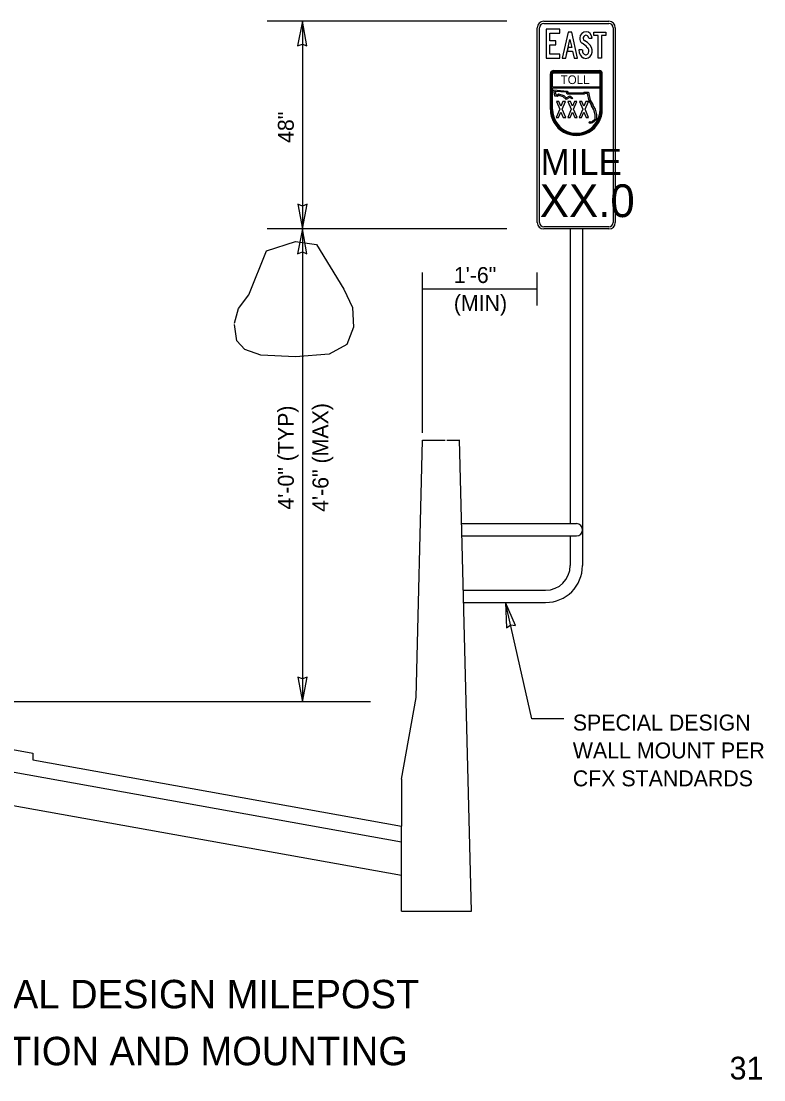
# Model space of a CAD drawing. Extents: x 57428 to 58066, y 11696 to 12105.
# Drawn here: x 57924.4 to 58054.8, y 11706.5 to 11892.4 of the extents above; entities that cross this region are included whole.
import ezdxf

# ---------------------------------------------------------------- set-up
doc = ezdxf.new("R2010")
doc.units = 0
for name, color, linetype in [('52', 7, 'Continuous'), ('62', 7, 'Continuous'), ('DimLines_dp', 7, 'Continuous'), ('NonPlottingEle_dp', 7, 'Continuous'), ('SheetLines_dp', 7, 'Continuous'), ('SignPanel', 7, 'Continuous'), ('TextMinor', 7, 'Continuous'), ('XSGrdLine_ex', 7, 'Continuous')]:
    doc.layers.add(name, color=color, linetype=linetype)

msp = doc.modelspace()

# ---------------------------------------------------------------- linework, layer by layer
at = {"layer": '52'}
msp.add_line((57985.74, 11772.84), (57842.57, 11772.84), dxfattribs=at)
at = {"layer": '62'}
msp.add_lwpolyline([(57961.87, 11839.32), (57962.57, 11841.92), (57964.37, 11844.33), (57967.47, 11852.08), (57972.57, 11853.68), (57976.27, 11853.18), (57981.07, 11845.33), (57982.58, 11842.12), (57982.78, 11838.62), (57981.57, 11835.62), (57978.47, 11833.91), (57972.57, 11833.41), (57966.47, 11833.71), (57963.67, 11834.71), (57962.27, 11836.22), (57961.87, 11839.12)], dxfattribs=at)
at = {"layer": 'DimLines_dp'}
for p, q in [((58009.68, 11892.38), (57967.6, 11892.38)), ((57973.78, 11892.38), (57972.94, 11888.03)), ((57973.78, 11892.38), (57973.78, 11855.89)), ((57974.59, 11888.03), (57973.78, 11892.38)), ((57972.94, 11888.03), (57973.78, 11888.36)), ((57973.78, 11888.36), (57974.59, 11888.03)), ((57973.78, 11861.88), (57973.78, 11772.84)), ((57973.78, 11859.91), (57972.97, 11860.24)), ((57972.97, 11860.24), (57973.78, 11855.89)), ((57973.78, 11859.91), (57972.97, 11860.24)), ((57972.97, 11860.24), (57973.78, 11855.89)), ((57973.78, 11855.89), (57974.62, 11860.24)), ((57974.62, 11860.24), (57973.78, 11859.91)), ((57973.78, 11855.89), (57974.62, 11860.24)), ((57974.62, 11860.24), (57973.78, 11859.91)), ((58009.68, 11855.89), (57967.6, 11855.89)), ((57973.78, 11855.89), (57972.94, 11851.54)), ((57974.59, 11851.54), (57973.78, 11855.89)), ((57972.94, 11851.54), (57973.78, 11851.87)), ((57973.78, 11851.87), (57974.59, 11851.54)), ((57994.89, 11820.11), (57994.89, 11848.22)), ((58015.03, 11842.47), (58015.03, 11848.22)), ((57994.89, 11845.38), (58015.03, 11845.38)), ((58009.47, 11790.29), (58009.6, 11785.87)), ((58011.21, 11786.23), (58009.47, 11790.29)), ((58014.05, 11769.85), (58009.47, 11790.29)), ((58009.6, 11785.87), (58010.35, 11786.37)), ((58010.35, 11786.37), (58011.21, 11786.23)), ((57973.78, 11776.86), (57972.97, 11777.19)), ((57972.97, 11777.19), (57973.78, 11772.84)), ((57973.78, 11772.84), (57974.62, 11777.19)), ((57974.62, 11777.19), (57973.78, 11776.86)), ((58019.7, 11769.85), (58014.05, 11769.85))]:
    msp.add_line(p, q, dxfattribs=at)
at = {"layer": 'NonPlottingEle_dp'}
for p, q in [((58020.8, 11855.89), (58020.8, 11804.14)), ((58022.96, 11855.89), (58022.96, 11796.77)), ((58001.72, 11804.14), (58021.88, 11804.14)), ((58001.78, 11801.98), (58021.88, 11801.98)), ((58020.8, 11801.98), (58020.8, 11796.77)), ((58002.02, 11792.45), (58016.48, 11792.45)), ((58002.08, 11790.29), (58016.48, 11790.29))]:
    msp.add_line(p, q, dxfattribs=at)
for centre, radius, end in [((58021.88, 11803.06), 1.08, 90), ((58016.48, 11796.77), 4.32, 0), ((58016.48, 11796.77), 6.48, 0)]:
    msp.add_arc(centre, radius, 270, end, dxfattribs=at)
at = {"layer": 'SignPanel'}
for p, q in [((58024.07, 11889.38), (58024.65, 11889.38)), ((58024.07, 11889.38), (58024.65, 11889.38)), ((58024.07, 11889.38), (58024.65, 11889.38)), ((58022.93, 11887.34), (58022.34, 11887.34)), ((58022.93, 11887.34), (58022.34, 11887.34)), ((58022.93, 11887.34), (58022.34, 11887.34)), ((58017.32, 11876.87), (58017.32, 11883.15)), ((58017.51, 11876.87), (58017.51, 11883.15)), ((58017.69, 11880.87), (58017.69, 11883.15)), ((58017.89, 11883.72), (58025.87, 11883.72)), ((58017.89, 11883.53), (58025.87, 11883.53)), ((58017.89, 11883.33), (58025.87, 11883.33)), ((58026.06, 11880.87), (58026.06, 11883.15)), ((58026.25, 11876.87), (58026.25, 11883.15)), ((58026.44, 11876.87), (58026.44, 11883.15)), ((58017.69, 11880.87), (58026.06, 11880.87)), ((58017.69, 11876.87), (58017.69, 11880.67)), ((58017.69, 11880.67), (58026.06, 11880.67)), ((58026.06, 11876.87), (58026.06, 11880.67)), ((58018.08, 11879.22), (58017.91, 11880.31)), ((58017.91, 11880.31), (58020.29, 11880.12)), ((58018.53, 11879.16), (58018.08, 11879.22)), ((58020.13, 11879.91), (58018.18, 11880.06)), ((58018.18, 11880.06), (58018.28, 11879.43)), ((58018.28, 11879.43), (58018.47, 11879.4)), ((58018.47, 11879.4), (58018.74, 11879.61)), ((58018.78, 11879.36), (58018.53, 11879.16)), ((58018.74, 11879.61), (58019.66, 11879.32)), ((58019.54, 11879.11), (58018.78, 11879.36)), ((58019.17, 11879.97), (58019.17, 11879.97)), ((58020.08, 11878.61), (58019.54, 11879.11)), ((58019.66, 11879.32), (58020.11, 11878.9)), ((58020.71, 11878.99), (58020.08, 11878.61)), ((58020.11, 11878.9), (58020.72, 11879.26)), ((58020.27, 11879.55), (58020.13, 11879.91)), ((58023.27, 11879.55), (58020.27, 11879.55)), ((58020.29, 11880.12), (58020.42, 11879.78)), ((58020.42, 11879.78), (58023.15, 11879.78)), ((58021.09, 11878.73), (58020.71, 11878.99)), ((58020.72, 11879.26), (58021.22, 11878.92)), ((58021.22, 11878.92), (58021.09, 11878.73)), ((58023.15, 11879.78), (58023.26, 11879.93)), ((58023.26, 11879.93), (58023.99, 11879.93)), ((58023.38, 11879.7), (58023.27, 11879.55)), ((58023.81, 11879.7), (58023.38, 11879.7)), ((58024.11, 11878.41), (58023.81, 11879.7)), ((58023.99, 11879.93), (58024.32, 11878.5)), ((58024.32, 11878.5), (58024.78, 11877.78)), ((58024.55, 11877.71), (58024.11, 11878.41)), ((58024.55, 11877.53), (58024.55, 11877.71)), ((58024.97, 11876.83), (58024.55, 11877.53)), ((58024.78, 11877.78), (58024.78, 11877.59)), ((58024.78, 11877.59), (58025.19, 11876.92)), ((58025.21, 11875.96), (58024.97, 11876.83)), ((58025.19, 11876.92), (58025.44, 11875.99)), ((58024.1, 11874.59), (58024.23, 11874.78)), ((58024.23, 11874.78), (58024.37, 11874.68)), ((58024.58, 11874.73), (58025.21, 11875.24)), ((58025.44, 11875.13), (58024.69, 11874.52)), ((58025.21, 11875.24), (58025.21, 11875.96)), ((58025.44, 11875.99), (58025.44, 11875.13)), ((58024.33, 11874.43), (58024.1, 11874.59)), ((58024.69, 11874.52), (58024.33, 11874.43)), ((58024.37, 11874.68), (58024.58, 11874.73))]:
    msp.add_line(p, q, dxfattribs=at)
for points in [[(58016.17, 11892.38), (58027.58, 11892.38)], [(58016.17, 11892), (58027.58, 11892)], [(58015.03, 11857.03), (58015.03, 11891.24)], [(58015.41, 11857.03), (58015.41, 11891.24)], [(58028.34, 11891.24), (58028.34, 11857.03)], [(58028.72, 11891.24), (58028.72, 11857.03)], [(58027.58, 11856.27), (58016.17, 11856.27)], [(58027.58, 11855.89), (58016.17, 11855.89)]]:
    msp.add_lwpolyline(points, dxfattribs=at)
for points in [[(58017.24, 11886.61), (58017.24, 11888.23), (58018.26, 11888.23), (58018.26, 11888.94), (58017.24, 11888.94), (58017.24, 11890.26), (58018.96, 11890.26), (58018.96, 11890.97), (58016.58, 11890.97), (58016.58, 11885.9), (58018.96, 11885.9), (58018.96, 11886.61)], [(58017.24, 11886.61), (58017.24, 11888.23), (58018.26, 11888.23), (58018.26, 11888.94), (58017.24, 11888.94), (58017.24, 11890.26), (58018.96, 11890.26), (58018.96, 11890.97), (58016.58, 11890.97), (58016.58, 11885.9), (58018.96, 11885.9), (58018.96, 11886.61)], [(58017.24, 11886.61), (58017.24, 11888.23), (58018.26, 11888.23), (58018.26, 11888.94), (58017.24, 11888.94), (58017.24, 11890.26), (58018.96, 11890.26), (58018.96, 11890.97), (58016.58, 11890.97), (58016.58, 11885.9), (58018.96, 11885.9), (58018.96, 11886.61)], [(58021.21, 11887.13), (58021.48, 11885.9), (58022.08, 11885.9), (58021.06, 11890.48), (58020.43, 11890.48), (58019.41, 11885.9), (58020.02, 11885.9), (58020.29, 11887.13)], [(58020.44, 11887.77), (58020.29, 11887.13), (58021.21, 11887.13), (58021.48, 11885.9), (58022.08, 11885.9), (58021.06, 11890.48), (58020.43, 11890.48), (58019.41, 11885.9), (58020.02, 11885.9), (58020.75, 11889.17), (58021.06, 11887.77)], [(58020.44, 11887.77), (58020.29, 11887.13), (58021.21, 11887.13), (58021.48, 11885.9), (58022.08, 11885.9), (58021.06, 11890.48), (58020.43, 11890.48), (58019.41, 11885.9), (58020.02, 11885.9), (58020.75, 11889.17), (58021.06, 11887.77)], [(58025.72, 11889.84), (58024.94, 11889.84), (58024.94, 11890.48), (58027.08, 11890.48), (58027.08, 11889.84), (58026.3, 11889.84), (58026.3, 11885.9), (58025.72, 11885.9)], [(58025.72, 11889.84), (58024.94, 11889.84), (58024.94, 11890.48), (58027.08, 11890.48), (58027.08, 11889.84), (58026.3, 11889.84), (58026.3, 11885.9), (58025.72, 11885.9)], [(58025.72, 11889.84), (58024.94, 11889.84), (58024.94, 11890.48), (58027.08, 11890.48), (58027.08, 11889.84), (58026.3, 11889.84), (58026.3, 11885.9), (58025.72, 11885.9)], [(58020.75, 11889.17), (58021.06, 11887.77), (58020.44, 11887.77)], [(58018.77, 11875.45), (58019.17, 11876.43), (58019.58, 11875.45), (58020.01, 11875.45), (58019.39, 11876.94), (58019.96, 11878.3), (58019.53, 11878.3), (58019.17, 11877.45), (58018.82, 11878.3), (58018.39, 11878.3), (58018.96, 11876.94), (58018.34, 11875.45)], [(58020.78, 11875.45), (58021.19, 11876.43), (58021.6, 11875.45), (58022.03, 11875.45), (58021.4, 11876.94), (58021.98, 11878.3), (58021.55, 11878.3), (58021.19, 11877.45), (58020.83, 11878.3), (58020.41, 11878.3), (58020.98, 11876.94), (58020.36, 11875.45)], [(58022.8, 11875.45), (58023.21, 11876.43), (58023.61, 11875.45), (58024.04, 11875.45), (58023.42, 11876.94), (58023.99, 11878.3), (58023.56, 11878.3), (58023.21, 11877.45), (58022.85, 11878.3), (58022.42, 11878.3), (58022.99, 11876.94), (58022.37, 11875.45)]]:
    msp.add_lwpolyline(points, close=True, dxfattribs=at)
for centre, radius, start, end in [((58016.17, 11891.24), 1.14, 90, 180), ((58016.17, 11891.24), 0.76, 90, 180), ((58027.58, 11891.24), 1.14, 0, 90), ((58027.58, 11891.24), 0.76, 0, 90), ((58016.17, 11857.03), 1.14, 180, 270), ((58016.17, 11857.03), 0.76, 180, 270), ((58027.58, 11857.03), 1.14, 270, 360), ((58027.58, 11857.03), 0.76, 270, 360)]:
    msp.add_arc(centre, radius, start, end, dxfattribs=at)
for centre, major_axis, ratio, start_param, end_param in [((58023.56, 11889.35), (0, 1.19), 0.91923, 4.736267, 7.790596), ((58023.56, 11889.35), (0, 1.19), 0.91923, 4.736267, 7.790596), ((58023.56, 11889.35), (0, 1.19), 0.91923, 4.736267, 7.790596), ((58023.49, 11889.41), (0, 0.46), 0.91923, 0.87378, 2.656959), ((58023.49, 11889.41), (0, 0.46), 0.91923, 0.87378, 2.656959), ((58023.49, 11889.41), (0, 0.46), 0.91923, 0.87378, 2.656959), ((58023.56, 11889.34), (0, 0.558), 0.91923, 4.786904, 7.140738), ((58023.56, 11889.34), (0, 0.558), 0.91923, 4.786904, 7.140738), ((58023.56, 11889.34), (0, 0.558), 0.91923, 4.786904, 7.140738), ((58023.45, 11889.39), (0, 1.07), 0.91923, 1.534831, 2.511766), ((58023.45, 11889.39), (0, 1.07), 0.91923, 1.534831, 2.511766), ((58023.45, 11889.39), (0, 1.07), 0.91923, 1.534831, 2.511766), ((58020.85, 11884.45), (0, 4.63), 0.91923, 5.515137, 5.786988), ((58020.85, 11884.45), (0, 4.63), 0.91923, 5.515137, 5.786988), ((58020.85, 11884.45), (0, 4.63), 0.91923, 5.515137, 5.786988), ((58021.36, 11885.15), (0, 4.39), 0.91923, 5.462886, 5.782242), ((58021.36, 11885.15), (0, 4.39), 0.91923, 5.462886, 5.782242), ((58021.36, 11885.15), (0, 4.39), 0.91923, 5.462886, 5.782242), ((58023.37, 11887.15), (0, 0.792), 0.91923, 4.254409, 5.632398), ((58023.37, 11887.15), (0, 0.792), 0.91923, 4.254409, 5.632398), ((58023.37, 11887.15), (0, 0.792), 0.91923, 4.254409, 5.632398), ((58023.38, 11887.15), (0, 1.42), 0.91923, 4.260987, 5.485755), ((58023.38, 11887.15), (0, 1.42), 0.91923, 4.260987, 5.485755), ((58023.38, 11887.15), (0, 1.42), 0.91923, 4.260987, 5.485755), ((58023.71, 11887.27), (0, 1.5), 0.91923, 1.526364, 2.701682), ((58023.71, 11887.27), (0, 1.5), 0.91923, 1.526364, 2.701682), ((58023.71, 11887.27), (0, 1.5), 0.91923, 1.526364, 2.701682), ((58023.77, 11887.3), (0, 0.911), 0.91923, 1.524757, 2.28214), ((58023.77, 11887.3), (0, 0.911), 0.91923, 1.524757, 2.28214), ((58023.77, 11887.3), (0, 0.911), 0.91923, 1.524757, 2.28214), ((58023.53, 11887.08), (0, 1.24), 0.91923, 2.786047, 4.251692), ((58023.53, 11887.08), (0, 1.24), 0.91923, 2.786047, 4.251692), ((58023.53, 11887.08), (0, 1.24), 0.91923, 2.786047, 4.251692), ((58023.55, 11887.07), (0, 0.581), 0.91923, 2.261787, 4.23006), ((58023.55, 11887.07), (0, 0.581), 0.91923, 2.261787, 4.23006), ((58023.55, 11887.07), (0, 0.581), 0.91923, 2.261787, 4.23006), ((58017.89, 11883.14), (0, 0.57), 0.9997, 0, 1.570796), ((58017.89, 11883.14), (0, 0.38), 0.9997, 0, 1.570796), ((58017.89, 11883.14), (0, 0.19), 0.9997, 0, 1.570796), ((58025.87, 11883.14), (0, 0.57), 0.9997, 4.712389, 6.283185), ((58025.87, 11883.14), (0, 0.38), 0.9997, 4.712389, 6.283185), ((58025.87, 11883.14), (0, 0.19), 0.9997, 4.712389, 6.283185), ((58021.88, 11876.87), (0, -4.56), 0.9997, 4.712389, 7.853982), ((58021.88, 11876.87), (0, -4.37), 0.9997, 4.712389, 7.853982), ((58021.88, 11876.87), (0, -4.18), 0.9997, 4.712389, 7.853982)]:
    msp.add_ellipse(centre, major_axis=major_axis, ratio=ratio, start_param=start_param, end_param=end_param, dxfattribs=at)
at = {"layer": 'XSGrdLine_ex'}
for p, q in [((57993.74, 11773.63), (57994.89, 11818.81)), ((57994.89, 11818.81), (57998.87, 11818.81)), ((57999.15, 11818.81), (58001.35, 11818.81)), ((58003.46, 11736.1), (58001.35, 11818.87)), ((57991.17, 11759.25), (57993.74, 11773.63)), ((57920.31, 11764.96), (57926.48, 11763.85)), ((57926.48, 11763.85), (57926.48, 11762.68)), ((57926.48, 11762.68), (57991.17, 11751.04)), ((57991.17, 11748.2), (57919.9, 11761.02)), ((57991.17, 11759.25), (57991.17, 11751.04)), ((57922.37, 11754.76), (57991.17, 11742.38)), ((57991.17, 11736.1), (57991.17, 11751.04)), ((57991.17, 11736.1), (58003.46, 11736.1))]:
    msp.add_line(p, q, dxfattribs=at)

# ---------------------------------------------------------------- texts
at = {"layer": 'DimLines_dp'}
for s, p in [('48"', (57972.28, 11871)), ('4\'-0" (TYP)', (57972.28, 11806.61)), ('4\'-6" (MAX)', (57978.36, 11806.21))]:
    msp.add_text(s, height=2.8, rotation=90, dxfattribs=at).set_placement(p)
for s, p in [('1\'-6"', (58000.37, 11846.4)), ('(MIN)', (58000.37, 11841.5)), ('SPECIAL DESIGN', (58021.26, 11767.81)), ('WALL MOUNT PER', (58021.26, 11762.91)), ('CFX STANDARDS', (58021.26, 11758.01))]:
    msp.add_text(s, height=2.8, dxfattribs=at).set_placement(p)
at = {"layer": 'SheetLines_dp'}
for s, p in [('SPECIAL DESIGN MILEPOST ', (57902.9, 11719.02)), (' LOCATION AND MOUNTING  ', (57902.04, 11709.02))]:
    msp.add_text(s, height=5, rotation=360, dxfattribs=at).set_placement(p)
at = {"layer": 'SignPanel'}
for s, height, p in [('TOLL', 1.519, (58019.12, 11881.34)), ('MILE', 4.562, (58015.62, 11865.39)), ('XX.0', 5.75, (58015.46, 11857.98))]:
    msp.add_text(s, height=height, rotation=360, dxfattribs=at).set_placement(p)
at = {"layer": 'TextMinor'}
msp.add_text('31', height=4, rotation=360, dxfattribs=at).set_placement((58048.78, 11706.52))

doc.saveas('drawing.dxf')
